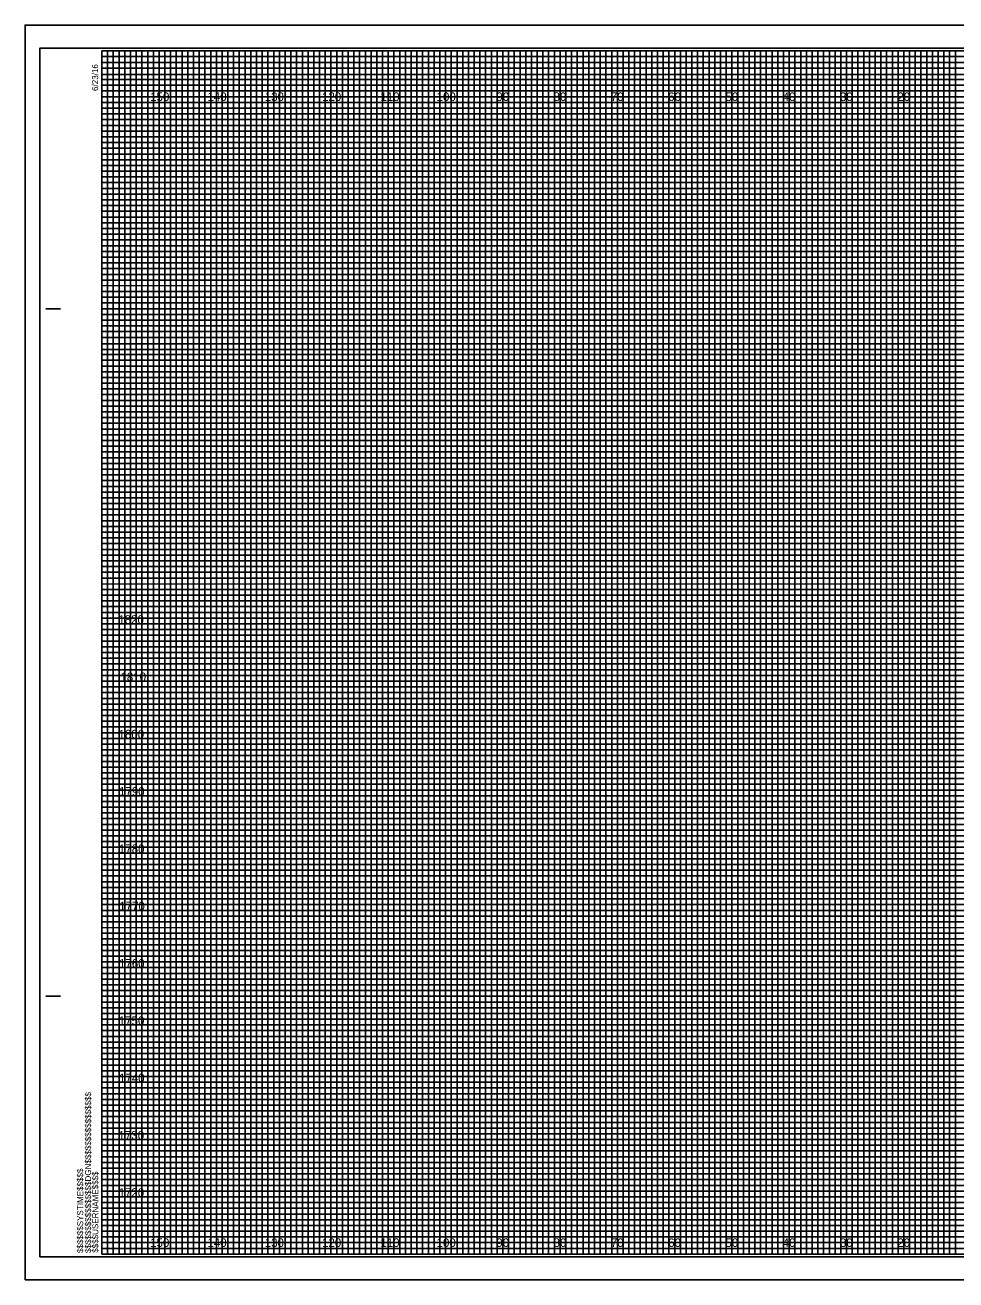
# Model space of a CAD drawing. Extents: x -15 to 323, y -5 to 6170.
# Drawn here: x -13.4 to 149.1, y 4395.5 to 4614.5 of the extents above; entities that cross this region are included whole.
import ezdxf

# ---------------------------------------------------------------- set-up
doc = ezdxf.new("R2010")
doc.units = 0
for name, color, linetype in [('Prop XS DDE', 7, 'Continuous'), ('Prop XS DDE Slope Text', 7, 'Continuous'), ('Prop XS DDE Text', 7, 'Continuous'), ('Prop XS Earthwork Shape', 7, 'Continuous'), ('Prop XS Noise Wall', 7, 'Continuous'), ('Prop XS Retaining Wall', 7, 'Continuous'), ('Prop XS Station Labels', 7, 'Continuous'), ('Scratch_Level_3', 7, 'Continuous'), ('Scratch_Level_7', 7, 'Continuous'), ('Scratch_Level_8', 7, 'Continuous'), ('Sheet Cross Section Grid Minor 1 CELL', 7, 'Continuous')]:
    doc.layers.add(name, color=color, linetype=linetype)

msp = doc.modelspace()

# ---------------------------------------------------------------- linework, layer by layer
at = {"layer": 'Prop XS DDE'}
msp.add_lwpolyline([(-13.4, 4395.5), (323.3, 4395.5), (323.3, 4614.5), (-13.4, 4614.5)], close=True, dxfattribs=at)
at = {"layer": 'Prop XS DDE Slope Text'}
msp.add_lwpolyline([(-10.8, 4399.5), (322.4, 4399.5), (322.4, 4610.5), (-10.8, 4610.5)], close=True, dxfattribs=at)
at = {"layer": 'Prop XS DDE Text'}
for p, q in [((10, 4400), (10, 4610)), ((20, 4400), (20, 4610)), ((30, 4400), (30, 4610)), ((40, 4400), (40, 4610)), ((50, 4400), (50, 4610)), ((60, 4400), (60, 4610)), ((70, 4400), (70, 4610)), ((80, 4400), (80, 4610)), ((90, 4400), (90, 4610)), ((100, 4400), (100, 4610)), ((110, 4400), (110, 4610)), ((120, 4400), (120, 4610)), ((130, 4400), (130, 4610)), ((140, 4400), (140, 4610)), ((0, 4600), (320, 4600)), ((0, 4590), (320, 4590)), ((0, 4580), (320, 4580)), ((0, 4570), (320, 4570)), ((0, 4560), (320, 4560)), ((0, 4550), (320, 4550)), ((0, 4540), (320, 4540)), ((0, 4530), (320, 4530)), ((0, 4520), (320, 4520)), ((0, 4510), (320, 4510)), ((0, 4500), (320, 4500)), ((0, 4490), (320, 4490)), ((0, 4480), (320, 4480)), ((0, 4470), (320, 4470)), ((0, 4460), (320, 4460)), ((0, 4450), (320, 4450)), ((0, 4440), (320, 4440)), ((0, 4430), (320, 4430)), ((0, 4420), (320, 4420)), ((0, 4410), (320, 4410))]:
    msp.add_line(p, q, dxfattribs=at)
at = {"layer": 'Prop XS Earthwork Shape'}
for p, q in [((10, 4610), (0, 4610)), ((10, 4400), (10, 4610)), ((30, 4610), (20, 4610)), ((20, 4610), (20, 4400)), ((30, 4400), (30, 4610)), ((50, 4610), (40, 4610)), ((40, 4610), (40, 4400)), ((50, 4400), (50, 4610)), ((70, 4610), (60, 4610)), ((60, 4610), (60, 4400)), ((70, 4400), (70, 4610)), ((90, 4610), (80, 4610)), ((80, 4610), (80, 4400)), ((90, 4400), (90, 4610)), ((110, 4610), (100, 4610)), ((100, 4610), (100, 4400)), ((110, 4400), (110, 4610)), ((130, 4610), (120, 4610)), ((120, 4610), (120, 4400)), ((130, 4400), (130, 4610)), ((150, 4610), (140, 4610)), ((140, 4610), (140, 4400)), ((20, 4400), (10, 4400)), ((40, 4400), (30, 4400)), ((60, 4400), (50, 4400)), ((80, 4400), (70, 4400)), ((100, 4400), (90, 4400)), ((120, 4400), (110, 4400)), ((140, 4400), (130, 4400))]:
    msp.add_line(p, q, dxfattribs=at)
for points in [[(0, 4600), (320, 4600), (320, 4590), (0, 4590)], [(0, 4580), (320, 4580), (320, 4570), (0, 4570)], [(0, 4560), (320, 4560), (320, 4550), (0, 4550)], [(0, 4540), (320, 4540), (320, 4530), (0, 4530)], [(0, 4520), (320, 4520), (320, 4510), (0, 4510)], [(0, 4500), (320, 4500), (320, 4490), (0, 4490)], [(0, 4480), (320, 4480), (320, 4470), (0, 4470)], [(0, 4460), (320, 4460), (320, 4450), (0, 4450)], [(0, 4440), (320, 4440), (320, 4430), (0, 4430)], [(0, 4420), (320, 4420), (320, 4410), (0, 4410)]]:
    msp.add_lwpolyline(points, dxfattribs=at)
at = {"layer": 'Prop XS Noise Wall'}
for p, q in [((-9.8, 4565), (-7.3, 4565)), ((-9.7, 4565), (-7.2, 4565)), ((-9.8, 4445), (-7.3, 4445)), ((-9.7, 4445), (-7.2, 4445)), ((0, 4400), (0, 4400)), ((0, 4400), (0, 4400)), ((0, 4400), (0, 4400)), ((0, 4400), (0, 4400)), ((0, 4400), (0, 4400)), ((0, 4400), (0, 4400)), ((0, 4400), (0, 4400))]:
    msp.add_line(p, q, dxfattribs=at)
msp.add_lwpolyline([(320, 4610), (0, 4610), (0, 4400), (320, 4400)], close=True, dxfattribs=at)
at = {"layer": 'Prop XS Retaining Wall'}
for points in [[(0, 4400), (1, 4400), (1, 4610), (2, 4610), (2, 4400)], [(2, 4400), (3, 4400), (3, 4610), (4, 4610), (4, 4400)], [(5, 4400), (6, 4400), (6, 4610), (7, 4610), (7, 4400)], [(7, 4400), (8, 4400), (8, 4610), (9, 4610), (9, 4400)], [(10, 4400), (11, 4400), (11, 4610), (12, 4610), (12, 4400)], [(12, 4400), (13, 4400), (13, 4610), (14, 4610), (14, 4400)], [(15, 4400), (16, 4400), (16, 4610), (17, 4610), (17, 4400)], [(17, 4400), (18, 4400), (18, 4610), (19, 4610), (19, 4400)], [(20, 4400), (21, 4400), (21, 4610), (22, 4610), (22, 4400)], [(22, 4400), (23, 4400), (23, 4610), (24, 4610), (24, 4400)], [(25, 4400), (26, 4400), (26, 4610), (27, 4610), (27, 4400)], [(27, 4400), (28, 4400), (28, 4610), (29, 4610), (29, 4400)], [(30, 4400), (31, 4400), (31, 4610), (32, 4610), (32, 4400)], [(32, 4400), (33, 4400), (33, 4610), (34, 4610), (34, 4400)], [(35, 4400), (36, 4400), (36, 4610), (37, 4610), (37, 4400)], [(37, 4400), (38, 4400), (38, 4610), (39, 4610), (39, 4400)], [(40, 4400), (41, 4400), (41, 4610), (42, 4610), (42, 4400)], [(42, 4400), (43, 4400), (43, 4610), (44, 4610), (44, 4400)], [(45, 4400), (46, 4400), (46, 4610), (47, 4610), (47, 4400)], [(47, 4400), (48, 4400), (48, 4610), (49, 4610), (49, 4400)], [(50, 4400), (51, 4400), (51, 4610), (52, 4610), (52, 4400)], [(52, 4400), (53, 4400), (53, 4610), (54, 4610), (54, 4400)], [(55, 4400), (56, 4400), (56, 4610), (57, 4610), (57, 4400)], [(57, 4400), (58, 4400), (58, 4610), (59, 4610), (59, 4400)], [(60, 4400), (61, 4400), (61, 4610), (62, 4610), (62, 4400)], [(62, 4400), (63, 4400), (63, 4610), (64, 4610), (64, 4400)], [(65, 4400), (66, 4400), (66, 4610), (67, 4610), (67, 4400)], [(67, 4400), (68, 4400), (68, 4610), (69, 4610), (69, 4400)], [(70, 4400), (71, 4400), (71, 4610), (72, 4610), (72, 4400)], [(72, 4400), (73, 4400), (73, 4610), (74, 4610), (74, 4400)], [(75, 4400), (76, 4400), (76, 4610), (77, 4610), (77, 4400)], [(77, 4400), (78, 4400), (78, 4610), (79, 4610), (79, 4400)], [(80, 4400), (81, 4400), (81, 4610), (82, 4610), (82, 4400)], [(82, 4400), (83, 4400), (83, 4610), (84, 4610), (84, 4400)], [(85, 4400), (86, 4400), (86, 4610), (87, 4610), (87, 4400)], [(87, 4400), (88, 4400), (88, 4610), (89, 4610), (89, 4400)], [(90, 4400), (91, 4400), (91, 4610), (92, 4610), (92, 4400)], [(92, 4400), (93, 4400), (93, 4610), (94, 4610), (94, 4400)], [(95, 4400), (96, 4400), (96, 4610), (97, 4610), (97, 4400)], [(97, 4400), (98, 4400), (98, 4610), (99, 4610), (99, 4400)], [(100, 4400), (101, 4400), (101, 4610), (102, 4610), (102, 4400)], [(102, 4400), (103, 4400), (103, 4610), (104, 4610), (104, 4400)], [(105, 4400), (106, 4400), (106, 4610), (107, 4610), (107, 4400)], [(107, 4400), (108, 4400), (108, 4610), (109, 4610), (109, 4400)], [(110, 4400), (111, 4400), (111, 4610), (112, 4610), (112, 4400)], [(112, 4400), (113, 4400), (113, 4610), (114, 4610), (114, 4400)], [(115, 4400), (116, 4400), (116, 4610), (117, 4610), (117, 4400)], [(117, 4400), (118, 4400), (118, 4610), (119, 4610), (119, 4400)], [(120, 4400), (121, 4400), (121, 4610), (122, 4610), (122, 4400)], [(122, 4400), (123, 4400), (123, 4610), (124, 4610), (124, 4400)], [(125, 4400), (126, 4400), (126, 4610), (127, 4610), (127, 4400)], [(127, 4400), (128, 4400), (128, 4610), (129, 4610), (129, 4400)], [(130, 4400), (131, 4400), (131, 4610), (132, 4610), (132, 4400)], [(132, 4400), (133, 4400), (133, 4610), (134, 4610), (134, 4400)], [(135, 4400), (136, 4400), (136, 4610), (137, 4610), (137, 4400)], [(137, 4400), (138, 4400), (138, 4610), (139, 4610), (139, 4400)], [(140, 4400), (141, 4400), (141, 4610), (142, 4610), (142, 4400)], [(142, 4400), (143, 4400), (143, 4610), (144, 4610), (144, 4400)], [(145, 4400), (146, 4400), (146, 4610), (147, 4610), (147, 4400)], [(147, 4400), (148, 4400), (148, 4610), (149, 4610), (149, 4400)]]:
    msp.add_lwpolyline(points, dxfattribs=at)
at = {"layer": 'Prop XS Station Labels'}
for points in [[(0, 4610), (5, 4610), (5, 4400), (15, 4400), (15, 4610), (25, 4610), (25, 4400), (35, 4400), (35, 4610), (45, 4610), (45, 4400), (55, 4400), (55, 4610), (65, 4610), (65, 4400), (75, 4400), (75, 4610), (85, 4610), (85, 4400), (95, 4400), (95, 4610), (105, 4610), (105, 4400), (115, 4400), (115, 4610), (125, 4610), (125, 4400), (135, 4400), (135, 4610), (145, 4610), (145, 4400), (155, 4400)], [(0, 4605), (275, 4605)], [(0, 4585), (320, 4585), (320, 4595), (0, 4595)], [(0, 4565), (320, 4565), (320, 4575), (0, 4575)], [(0, 4545), (320, 4545), (320, 4555), (0, 4555)], [(0, 4525), (320, 4525), (320, 4535), (0, 4535)], [(0, 4505), (320, 4505), (320, 4515), (0, 4515)], [(0, 4485), (320, 4485), (320, 4495), (0, 4495)], [(0, 4465), (320, 4465), (320, 4475), (0, 4475)], [(0, 4445), (320, 4445), (320, 4455), (0, 4455)], [(0, 4425), (320, 4425), (320, 4435), (0, 4435)], [(0, 4405), (320, 4405), (320, 4415), (0, 4415)]]:
    msp.add_lwpolyline(points, dxfattribs=at)
at = {"layer": 'Scratch_Level_7'}
for p, q in [((323.3, 4614.5), (-13.4, 4614.5)), ((-13.4, 4614.5), (-13.4, 4395.5)), ((-13.4, 4395.5), (323.3, 4395.5))]:
    msp.add_line(p, q, dxfattribs=at)
at = {"layer": 'Sheet Cross Section Grid Minor 1 CELL'}
for p, q in [((0, 4609), (260, 4609)), ((260, 4607.98), (0, 4607.98)), ((0, 4607.98), (0, 4607)), ((0, 4607), (260, 4607)), ((260, 4605.89), (0, 4605.89)), ((0, 4605.89), (0, 4604)), ((0, 4604), (320, 4604))]:
    msp.add_line(p, q, dxfattribs=at)
for points in [[(0, 4603), (270, 4603), (320, 4603), (320, 4602), (0, 4602)], [(0, 4601), (320, 4601), (320, 4599), (0, 4599)], [(0, 4598), (320, 4598), (320, 4597), (0, 4596.98)], [(0, 4596), (320, 4596), (320, 4594), (0, 4594)], [(0, 4593), (320, 4593), (320, 4592), (0, 4592)], [(0, 4591), (320, 4591), (320, 4589), (0, 4589)], [(0, 4588), (320, 4588), (320, 4587), (0, 4587)], [(0, 4586), (320, 4586), (320, 4584), (0, 4584)], [(0, 4583), (320, 4583), (320, 4582), (0, 4582)], [(0, 4581), (320, 4581), (320, 4579), (0, 4579)], [(0, 4578), (320, 4578), (320, 4577), (0, 4577)], [(0, 4576), (320, 4576), (320, 4573.95), (320, 4573), (320, 4572), (0, 4572)], [(0, 4574), (320, 4574), (320, 4573), (0, 4573)], [(0, 4571), (320, 4571), (320, 4569), (0, 4569.03)], [(0, 4569.03), (320, 4569), (320, 4568), (0, 4568)], [(0, 4567), (320, 4567), (320, 4566), (0, 4566)], [(0, 4564), (320, 4564), (320, 4563), (0, 4563)], [(0, 4562), (320, 4562), (320, 4561), (0, 4561)], [(-0.07, 4558.89), (320, 4558.89), (320, 4557.88), (-0.07, 4557.88)], [(0, 4557), (320, 4557), (320, 4556), (0, 4556)], [(0, 4554), (320, 4554), (320, 4553), (0, 4553)], [(0, 4552), (320, 4552), (320, 4551), (0, 4551)], [(0, 4549), (320, 4549), (320, 4548), (0, 4548)], [(0, 4547), (320, 4547), (320, 4546), (0, 4546)], [(0, 4544), (320, 4544), (320, 4543), (0, 4543)], [(0, 4542), (320, 4542), (320, 4541), (0, 4541)], [(0, 4539), (320, 4539), (319.99, 4537.98), (0, 4538)], [(0, 4537), (320, 4537), (320, 4536), (0, 4536)], [(0, 4534), (320, 4534), (320, 4533), (0, 4533)], [(0, 4532), (320, 4532), (320, 4531), (0, 4531)], [(0, 4529), (320, 4529), (320, 4528), (0, 4528)], [(0, 4527), (320, 4527), (320, 4526), (0, 4526)], [(0, 4524), (320, 4524), (320, 4523), (0, 4523)], [(0, 4522), (320, 4522), (320, 4521), (0, 4521)], [(0, 4519), (320, 4519), (320, 4518), (0, 4518)], [(0, 4516.99), (320.07, 4516.91), (320, 4516), (0, 4516)], [(0, 4514), (320, 4514), (320, 4513), (0, 4513)], [(0, 4512), (320, 4512), (320, 4511), (0, 4511)], [(0, 4509), (320, 4509), (320, 4508), (0, 4508)], [(0, 4507), (320, 4507), (320, 4506), (0, 4506)], [(0, 4504), (320, 4504), (320, 4503), (0, 4503)], [(0, 4502), (320, 4502), (320, 4501), (0, 4501)], [(0, 4499), (320, 4499), (320, 4498), (0, 4498)], [(0, 4497), (320, 4497), (320, 4496), (0, 4496)], [(0, 4494), (320, 4494), (320, 4493), (0, 4493)], [(0, 4492), (320, 4492), (320, 4491), (0, 4491)], [(0, 4489), (320, 4489), (320, 4488), (0, 4488)], [(0, 4487), (320, 4487), (320, 4486), (0, 4486)], [(0, 4484), (320, 4484), (320, 4483), (0, 4483)], [(0, 4482), (320, 4482), (320, 4481), (0, 4481)], [(0, 4479), (320, 4479), (319.99, 4477.98), (0, 4478)], [(0, 4477), (320, 4477), (320, 4476), (0, 4476)], [(0, 4474), (320, 4474), (320, 4473), (0, 4473)], [(0, 4472), (320, 4472), (320, 4471), (0, 4471)], [(0, 4469), (320, 4469), (320, 4468), (0, 4468)], [(0, 4467), (320, 4467), (320, 4466), (0, 4466)], [(0, 4464), (320, 4464), (320, 4463), (0, 4463)], [(0, 4462), (320, 4462), (320, 4461), (0, 4461)], [(0, 4459), (320, 4459), (320, 4458), (0, 4458)], [(0, 4456.99), (320.07, 4456.91), (320, 4456), (0, 4456)], [(0, 4454), (320, 4454), (320, 4453), (0, 4453)], [(0, 4452), (320, 4452), (320, 4451), (0, 4451)], [(0, 4449), (320, 4449), (320, 4448), (0, 4448)], [(0, 4447), (320, 4447), (320, 4446), (0, 4446)], [(0, 4444), (320, 4444), (320, 4443), (0, 4443)], [(0, 4442), (320, 4442), (320, 4441), (0, 4441)], [(0, 4439), (320, 4439), (320, 4438), (0, 4438)], [(0, 4437), (320, 4437), (320, 4436), (0, 4436)], [(0, 4434), (320, 4434), (320, 4433), (0, 4433)], [(0, 4432), (320, 4432), (320, 4431), (0, 4431)], [(0, 4429), (320, 4429), (320, 4428), (0, 4428)], [(0, 4427), (320, 4427), (320, 4426), (0, 4426)], [(0, 4424), (320, 4424), (320, 4423), (0, 4423)], [(0, 4422), (320, 4422), (320, 4421), (0, 4421)], [(0, 4419), (320, 4419), (320, 4418), (0, 4418)], [(0, 4417), (320, 4417), (320, 4416), (0, 4416)], [(0, 4414), (320, 4414), (320, 4413), (0, 4413)], [(0, 4412), (320, 4412), (320, 4411), (0, 4411)], [(0, 4409), (320, 4409), (320, 4408), (0, 4408)], [(0, 4407), (320, 4407), (320, 4406), (0, 4406)], [(0, 4404), (320, 4404), (320, 4403), (0, 4403)], [(0, 4402), (320, 4402), (320, 4401), (0, 4401)]]:
    msp.add_lwpolyline(points, dxfattribs=at)

# ---------------------------------------------------------------- texts
at = {"layer": 'Prop XS Noise Wall'}
for s, p in [('6/23/16', (-0.65, 4603)), ('$$$$$$$$$$$$$$$$DGN$$$$$$$$$$$$$$$$', (-1.88, 4400.18)), ('$$$$$$SYSTIME$$$$$', (-3.26, 4400.18)), ('$$$$USERNAME$$$$', (-0.62, 4400.23))]:
    msp.add_text(s, height=1.05, rotation=90, dxfattribs=at).set_placement(p)
at = {"layer": 'Scratch_Level_3'}
for s, p in [('1820', (2.87, 4510)), ('1810', (3.25, 4500)), ('1800', (2.92, 4490)), ('1790', (3, 4480)), ('1780', (2.98, 4470)), ('1770', (3.04, 4460)), ('1760', (3, 4450)), ('1750', (2.96, 4440)), ('1740', (3, 4430)), ('1730', (2.92, 4420)), ('1720', (2.93, 4410))]:
    msp.add_text(s, height=1.5, dxfattribs=at).set_placement(p)
at = {"layer": 'Scratch_Level_8'}
for s, p in [('150', (8.44, 4601.25)), ('140', (18.44, 4601.25)), ('130', (28.44, 4601.25)), ('120', (38.44, 4601.25)), ('110', (48.62, 4601.25)), ('100', (58.44, 4601.25)), ('90', (68.86, 4601.25)), ('80', (78.86, 4601.25)), ('70', (88.86, 4601.25)), ('60', (98.86, 4601.25)), ('50', (108.86, 4601.25)), ('40', (118.86, 4601.25)), ('30', (128.86, 4601.25)), ('20', (138.86, 4601.25)), ('150', (8.44, 4401.25)), ('140', (18.44, 4401.25)), ('130', (28.44, 4401.25)), ('120', (38.44, 4401.25)), ('110', (48.62, 4401.25)), ('100', (58.44, 4401.25)), ('90', (68.86, 4401.25)), ('80', (78.86, 4401.25)), ('70', (88.86, 4401.25)), ('60', (98.86, 4401.25)), ('50', (108.86, 4401.25)), ('40', (118.86, 4401.25)), ('30', (128.86, 4401.25)), ('20', (138.86, 4401.25))]:
    msp.add_text(s, height=1.5, dxfattribs=at).set_placement(p)

doc.saveas('drawing.dxf')
